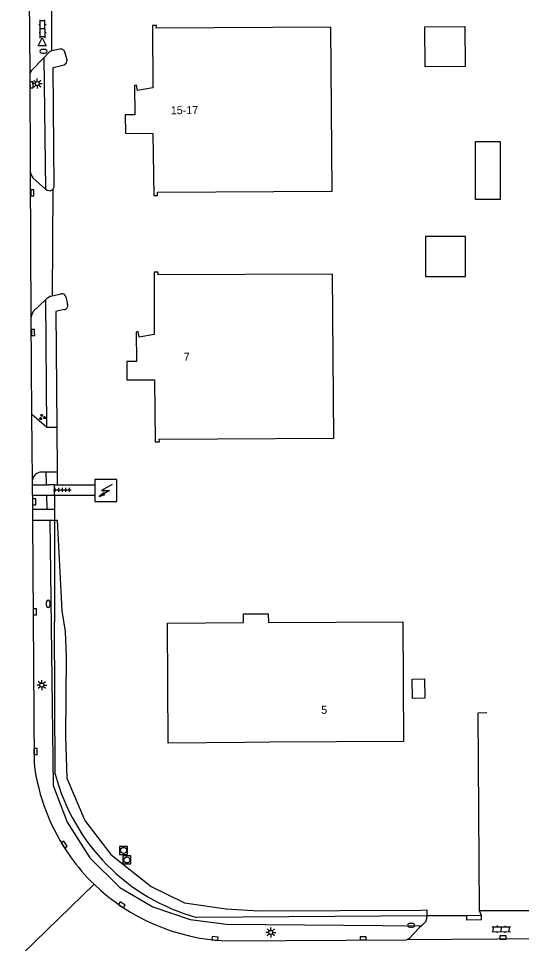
# Model space of a CAD drawing. Extents: x 131000 to 133013, y 393000 to 396501.
# Drawn here: x 132118.8 to 132181.7, y 394804.8 to 394920.3 of the extents above; entities that cross this region are included whole.
import ezdxf

# ---------------------------------------------------------------- set-up
doc = ezdxf.new("R2010")
doc.units = 0
for name, color, linetype in [('gg-afsc-erfafscheiding', 7, 'Continuous'), ('gg-afsc-hekwerk', 7, 'Continuous'), ('gg-anno-huisnummerreeks BGT', 7, 'Continuous'), ('gg-bbg-gedigitaliseerde bebouwing', 7, 'Continuous'), ('gg-bbg-gedigitaliseerde bijgebouw', 7, 'Continuous'), ('gg-bbg-hoofdgebouw', 7, 'Continuous'), ('gg-bbg-lage trafo', 7, 'Continuous'), ('gg-bbg-overig bouwwerk', 7, 'Continuous'), ('gg-bbg-toegangstrap', 7, 'Continuous'), ('gg-knt-verharding', 7, 'Continuous'), ('gt-grn-groengrens', 7, 'Continuous'), ('gt-grn-vlakafsluiter', 7, 'Continuous'), ('gt-grn-weggrens', 7, 'Continuous'), ('gt-symb-brandkraan', 7, 'Continuous'), ('gt-symb-groenvak', 7, 'Continuous'), ('gt-symb-klinker verharding', 7, 'Continuous'), ('gt-symb-kolk', 7, 'Continuous'), ('gt-symb-lichtmast', 7, 'Continuous'), ('gt-symb-rioolschacht', 7, 'Continuous'), ('gt-symb-tegel verharding', 7, 'Continuous'), ('gt-symb-trafo symbool', 7, 'Continuous'), ('gt-symb-waterafsluiter', 7, 'Continuous')]:
    doc.layers.add(name, color=color, linetype=linetype)

# ---------------------------------------------------------------- blocks, each defined once
blk = doc.blocks.new('gt0-GRVAK')
at = {"layer": 'gt-symb-groenvak'}
for p, q in [((-0.11, 0.19), (-0.23, 0.24)), ((-0.18, 0.15), (0.09, 0.15)), ((-0.09, 0.21), (-0.16, 0.32)), ((-0.05, 0.21), (-0.05, 0.39)), ((0, 0.21), (0.06, 0.32)), ((0.02, 0.19), (0.13, 0.24)), ((0.26, -0.05), (0.2, 0.06)), ((0.31, -0.05), (0.31, 0.13)), ((0.35, -0.05), (0.41, 0.06)), ((-0.24, -0.23), (-0.36, -0.18)), ((-0.32, -0.26), (-0.05, -0.26)), ((-0.23, -0.21), (-0.29, -0.09)), ((-0.18, -0.2), (-0.18, -0.02)), ((-0.14, -0.21), (-0.07, -0.09)), ((-0.12, -0.23), (0, -0.18)), ((0.24, -0.07), (0.12, -0.02)), ((0.17, -0.11), (0.44, -0.11)), ((0.37, -0.07), (0.49, -0.02))]:
    blk.add_line(p, q, dxfattribs=at)
blk = doc.blocks.new('gt0-KOLK')
at = {"layer": 'gt-symb-kolk'}
blk.add_lwpolyline([(0, 0), (0.37, 0), (0.37, 0.4), (-0.38, 0.4), (-0.38, 0), (0, 0)], dxfattribs=at)
blk = doc.blocks.new('gt0-KL1')
at = {"layer": 'gt-symb-klinker verharding'}
for p, q in [((-1.15, 0.3), (1.15, 0.3)), ((-1, -0.3), (-1, 0.3)), ((-0.5, 0.3), (-0.5, 0.45)), ((0, -0.3), (0, 0.3)), ((0.5, 0.3), (0.5, 0.45)), ((1, -0.3), (1, 0.3)), ((-1.15, -0.3), (1.15, -0.3)), ((-0.5, -0.45), (-0.5, -0.3)), ((0.5, -0.45), (0.5, -0.3))]:
    blk.add_line(p, q, dxfattribs=at)
blk = doc.blocks.new('gt0-LMAST')
at = {"layer": 'gt-symb-lichtmast'}
for p, q in [((-0.18, 0.17), (-0.45, 0.44)), ((-0.01, 0.25), (-0.01, 0.62)), ((0.17, 0.17), (0.44, 0.44)), ((-0.26, 0), (-0.63, 0)), ((-0.18, -0.18), (-0.45, -0.45)), ((-0.01, -0.25), (-0.01, -0.63)), ((0.44, -0.45), (0.17, -0.18)), ((0.24, 0), (0.62, 0))]:
    blk.add_line(p, q, dxfattribs=at)
blk.add_circle((-0.01, 0), 0.25, dxfattribs=at)
blk = doc.blocks.new('gt0-BR')
at = {"layer": 'gt-symb-brandkraan'}
for centre, radius, start, end in [((-0.24, 0), 0.206, 107.5669, 252.4331), ((0.6, -2.66), 3, 106.892, 107.5669), ((0, -0.69), 0.938, 73.108, 106.892), ((-0.6, -2.66), 3, 72.4331, 73.108), ((0.24, 0), 0.206, 287.567, 72.4331), ((0.6, 2.66), 3, 252.4331, 253.108), ((0, 0.69), 0.938, 253.108, 286.8921), ((-0.6, 2.66), 3, 286.8921, 287.567)]:
    blk.add_arc(centre, radius, start, end, dxfattribs=at)
blk = doc.blocks.new('gt0-TEG1')
at = {"layer": 'gt-symb-tegel verharding'}
for p, q in [((-1.12, 0), (1.12, 0)), ((-0.9, -0.25), (-0.9, 0.25)), ((-0.45, -0.25), (-0.45, 0.25)), ((0, -0.25), (0, 0.25)), ((0.45, -0.25), (0.45, 0.25)), ((0.9, -0.25), (0.9, 0.25))]:
    blk.add_line(p, q, dxfattribs=at)
blk = doc.blocks.new('gt0-HSP')
at = {"layer": 'gt-symb-trafo symbool'}
for points in [[(0.77, 0.75), (-0.53, 0), (0.47, 0), (-0.83, -0.75)], [(-0.22, -0.24), (-0.83, -0.75), (-0.08, -0.48)]]:
    blk.add_lwpolyline(points, dxfattribs=at)
blk = doc.blocks.new('gt0-WAFSL')
at = {"layer": 'gt-symb-waterafsluiter'}
for p, q in [((-0.5, -0.33), (0, 0.67)), ((0, 0.67), (0.5, -0.33)), ((0.5, -0.33), (-0.5, -0.33))]:
    blk.add_line(p, q, dxfattribs=at)
blk = doc.blocks.new('gt0-RS')
at = {"layer": 'gt-symb-rioolschacht'}
blk.add_lwpolyline([(-0.5, -0.5), (0.5, -0.5), (0.5, 0.5), (-0.5, 0.5)], close=True, dxfattribs=at)
blk.add_circle((0, 0), 0.375, dxfattribs=at)

msp = doc.modelspace()

# ---------------------------------------------------------------- linework, layer by layer
at = {"layer": 'gg-afsc-erfafscheiding'}
for p, q in [((132123.42, 394825.9), (132123.31, 394844.96)), ((132169.85, 394808.2), (132141.09, 394808.02)), ((132174.82, 394808.23), (132169.85, 394808.2)), ((132176.64, 394808.24), (132174.82, 394808.23))]:
    msp.add_line(p, q, dxfattribs=at)
msp.add_arc((132147.81, 394832.32), 25.22, 194.7562, 254.554, dxfattribs=at)
at = {"layer": 'gg-afsc-hekwerk'}
msp.add_line((132183.21, 394808.86), (132176.43, 394808.82), dxfattribs=at)
msp.add_lwpolyline([(132176.43, 394808.82), (132176.23, 394833.59), (132177.33, 394833.6)], dxfattribs=at)
at = {"layer": 'gg-bbg-gedigitaliseerde bebouwing'}
msp.add_lwpolyline([(132146.94, 394844.84), (132146.93, 394845.94), (132150.03, 394845.96), (132150.04, 394844.86)], dxfattribs=at)
at = {"layer": 'gg-bbg-gedigitaliseerde bijgebouw'}
for points in [[(132169.61, 394914.28), (132169.57, 394919.28), (132174.57, 394919.32), (132174.61, 394914.32), (132169.61, 394914.28)], [(132175.92, 394904.96), (132178.99, 394904.96), (132178.99, 394897.69), (132175.92, 394897.69), (132175.92, 394904.96)]]:
    msp.add_lwpolyline(points, dxfattribs=at)
at = {"layer": 'gg-bbg-hoofdgebouw'}
for points in [[(132136.04, 394919.09), (132136.06, 394919.43), (132135.56, 394919.43), (132135.61, 394911.66), (132133.71, 394911.33), (132133.55, 394912), (132133.32, 394911.96), (132133.37, 394908.27), (132132.17, 394908.28), (132132.18, 394905.97), (132135.63, 394905.95), (132135.72, 394898.22), (132136.21, 394898.22), (132136.2, 394898.61), (132158, 394898.75), (132157.84, 394919.23), (132136.04, 394919.09)], [(132136.26, 394888.29), (132136.26, 394888.64), (132135.79, 394888.64), (132135.76, 394880.85), (132133.91, 394880.51), (132133.76, 394881.19), (132133.53, 394881.13), (132133.56, 394877.47), (132132.37, 394877.45), (132132.38, 394875.16), (132135.83, 394875.16), (132135.92, 394867.41), (132136.43, 394867.42), (132136.42, 394867.77), (132158.22, 394867.9), (132158.06, 394888.38), (132136.26, 394888.29)], [(132150.04, 394844.86), (132166.84, 394844.95), (132166.92, 394829.99), (132150.18, 394829.92), (132147.06, 394829.86), (132137.54, 394829.79), (132137.45, 394844.79), (132146.94, 394844.84)]]:
    msp.add_lwpolyline(points, dxfattribs=at)
at = {"layer": 'gg-bbg-lage trafo'}
msp.add_line((132128.35, 394862.07), (132128.35, 394860.77), dxfattribs=at)
msp.add_lwpolyline([(132128.35, 394860.77), (132128.35, 394859.97), (132131.11, 394859.97), (132131.11, 394862.72), (132128.35, 394862.71), (132128.35, 394862.07)], dxfattribs=at)
at = {"layer": 'gg-bbg-overig bouwwerk'}
msp.add_lwpolyline([(132169.68, 394893.08), (132169.68, 394888.09), (132174.67, 394888.09), (132174.67, 394893.08), (132169.68, 394893.08)], dxfattribs=at)
at = {"layer": 'gg-bbg-toegangstrap'}
msp.add_lwpolyline([(132168, 394837.78), (132169.56, 394837.81), (132169.6, 394835.4), (132168.04, 394835.38), (132168, 394837.78)], dxfattribs=at)
at = {"layer": 'gg-knt-verharding'}
for p, q in [((132120.27, 394913.5), (132120.21, 394923.58)), ((132122.94, 394921.21), (132122.94, 394916.26)), ((132124, 394916.48), (132122.94, 394916.26)), ((132120.32, 394901.09), (132120.27, 394913.5)), ((132120.41, 394883), (132120.32, 394901.09)), ((132123.13, 394898.93), (132123.05, 394885.68)), ((132123.05, 394885.68), (132124.14, 394885.92)), ((132124.74, 394885.54), (132124.97, 394884.56)), ((132120.5, 394870.84), (132120.41, 394883)), ((132120.56, 394862.7), (132120.5, 394870.84)), ((132122.31, 394869.24), (132120.5, 394870.84)), ((132122.31, 394869.24), (132123.61, 394869.25)), ((132123.61, 394869.25), (132123.65, 394863.68)), ((132121.68, 394863.66), (132122.24, 394863.67)), ((132122.24, 394863.67), (132123.65, 394863.68)), ((132123.65, 394863.68), (132123.67, 394862.07)), ((132120.57, 394862.07), (132120.56, 394862.7)), ((132120.57, 394860.77), (132120.57, 394862.07)), ((132120.57, 394862.07), (132122.28, 394862.07)), ((132122.28, 394862.07), (132122.58, 394862.07)), ((132123.34, 394862.07), (132122.58, 394862.07)), ((132123.34, 394862.07), (132123.67, 394862.07)), ((132123.67, 394862.07), (132128.35, 394862.07)), ((132120.57, 394860.77), (132120.58, 394859.01)), ((132120.57, 394860.77), (132122.06, 394860.77)), ((132122.06, 394860.77), (132122.31, 394860.77)), ((132122.31, 394860.77), (132123.34, 394860.77)), ((132123.34, 394860.77), (132128.35, 394860.77)), ((132120.58, 394859.01), (132120.59, 394857.65)), ((132120.58, 394859.01), (132122.36, 394859.01)), ((132122.36, 394859.01), (132123.34, 394859.01)), ((132120.59, 394857.65), (132122.75, 394857.65)), ((132120.59, 394857.65), (132120.77, 394827.29)), ((132122.75, 394857.65), (132123.33, 394857.65)), ((132123.33, 394857.65), (132123.67, 394857.64)), ((132169.83, 394807.97), (132169.85, 394808.2)), ((132174.82, 394807.68), (132174.82, 394808.23)), ((132176.65, 394807.7), (132176.64, 394808.24)), ((132169.16, 394806.97), (132168.93, 394806.74)), ((132176.65, 394807.7), (132174.82, 394807.68)), ((132144.72, 394805.09), (132167.29, 394805.23)), ((132185.25, 394805.35), (132167.29, 394805.23))]:
    msp.add_line(p, q, dxfattribs=at)
for points in [[(132122, 394915.41), (132120.43, 394913.76), (132120.27, 394913.5)], [(132122.94, 394916.26), (132122.7, 394916.15), (132122, 394915.41)], [(132123.13, 394898.93), (132123.28, 394899.28), (132123.18, 394914.17), (132124.52, 394914.53), (132124.82, 394914.77), (132124.89, 394915.14), (132124.63, 394916.12)], [(132120.32, 394901.09), (132120.4, 394900.72), (132120.62, 394900.4), (132122.2, 394899)], [(132122.2, 394899), (132122.41, 394898.87), (132122.79, 394898.79), (132123.13, 394898.93)], [(132122.2, 394885.16), (132122.46, 394885.4), (132122.78, 394885.62), (132123.05, 394885.68)], [(132122.2, 394885.16), (132120.7, 394883.73), (132120.48, 394883.39), (132120.41, 394883)], [(132124.54, 394883.95), (132123.49, 394883.69), (132123.61, 394869.25)], [(132169.83, 394807.97), (132169.81, 394807.82), (132169.65, 394807.48), (132169.16, 394806.97)], [(132168.93, 394806.74), (132167.58, 394805.35), (132167.29, 394805.23)]]:
    msp.add_lwpolyline(points, dxfattribs=at)
for centre, radius, start, end in [((132124.13, 394915.99), 0.513, 14.586, 105.4769), ((132124.25, 394885.43), 0.501, 13.1763, 103.036), ((132124.54, 394884.41), 0.451, 270.0836, 20.0848), ((132121.75, 394862.45), 1.21, 93.166, 168.1294), ((132145.82, 394830.29), 25.22, 186.8141, 215.6538), ((132145.77, 394830.25), 25.17, 215.6512, 225.9318), ((132145.81, 394830.29), 25.22, 225.9195, 267.5203)]:
    msp.add_arc(centre, radius, start, end, dxfattribs=at)
at = {"layer": 'gt-grn-groengrens'}
for p, q in [((132122, 394915.41), (132122.2, 394899)), ((132122.2, 394885.16), (132122.31, 394869.24)), ((132122.24, 394863.67), (132122.28, 394862.07)), ((132122.31, 394860.77), (132122.36, 394859.01))]:
    msp.add_line(p, q, dxfattribs=at)
for points in [[(132122.75, 394857.65), (132123.16, 394824.48), (132124.9, 394819.92), (132127.74, 394815.47), (132131.48, 394811.76), (132135.59, 394809.35), (132140.27, 394807.75), (132144.83, 394807.16), (132169.16, 394806.97)], [(132123.67, 394857.64), (132124.26, 394846.33), (132124.67, 394843.74), (132124.79, 394840.57), (132124.69, 394830.62), (132124.85, 394825.43), (132127.1, 394820.12), (132130.37, 394815.89), (132135.39, 394811.9), (132139.57, 394809.84), (132144.77, 394809.07), (132148.82, 394808.85), (132169.09, 394808.94)]]:
    msp.add_lwpolyline(points, dxfattribs=at)
at = {"layer": 'gt-grn-vlakafsluiter'}
for p, q in [((132123.34, 394860.77), (132123.34, 394859.01)), ((132123.34, 394859.01), (132123.33, 394857.65)), ((132123.33, 394857.65), (132123.31, 394844.96)), ((132176.64, 394808.24), (132176.43, 394808.82))]:
    msp.add_line(p, q, dxfattribs=at)
msp.add_lwpolyline([(132169.09, 394808.94), (132169.84, 394808.95), (132169.85, 394808.2)], dxfattribs=at)
at = {"layer": 'gt-grn-weggrens'}
for p, q in [((132123.34, 394860.77), (132123.34, 394862.07)), ((132117.22, 394801.42), (132128.27, 394812.17))]:
    msp.add_line(p, q, dxfattribs=at)

# ---------------------------------------------------------------- block references
at = {"layer": 'gt-symb-brandkraan'}
for p in [(132121.96, 394916.21), (132167.88, 394807.03)]:
    msp.add_blockref('gt0-BR', p, dxfattribs=at)
at = {"layer": 'gt-symb-brandkraan', "rotation": 90.45835645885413}
msp.add_blockref('gt0-BR', (132122.54, 394847.19), dxfattribs=at)
at = {"layer": 'gt-symb-groenvak'}
msp.add_blockref('gt0-GRVAK', (132121.8, 394870.51), dxfattribs=at)
at = {"layer": 'gt-symb-klinker verharding'}
for p, rotation in [((132121.84, 394919.01), 90.68751635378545), ((132179.14, 394806.54), -0.9739344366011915)]:
    msp.add_blockref('gt0-KL1', p, dxfattribs=dict(at, rotation=rotation))
at = {"layer": 'gt-symb-kolk'}
for p, rotation in [((132120.67, 394912.02), 90.45835645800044), ((132120.76, 394898.54), 90.45835645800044), ((132120.85, 394881.09), 90.45835645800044), ((132120.58, 394859.94), -89.66107117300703), ((132121.07, 394846.21), 90.45835645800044), ((132121.16, 394828.74), 90.45835645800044), ((132124.37, 394817), -57.24756055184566), ((132131.63, 394809.43), -33.578813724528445), ((132143.37, 394805.18), -6.200970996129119)]:
    msp.add_blockref('gt0-KOLK', p, dxfattribs=dict(at, rotation=rotation))
for p in [(132161.88, 394805.21), (132179.35, 394805.32)]:
    msp.add_blockref('gt0-KOLK', p, dxfattribs=at)
at = {"layer": 'gt-symb-lichtmast'}
for p in [(132121.18, 394912.18), (132121.75, 394837.05), (132150.35, 394806.15)]:
    msp.add_blockref('gt0-LMAST', p, dxfattribs=at)
at = {"layer": 'gt-symb-rioolschacht'}
for p in [(132131.96, 394816.39), (132132.37, 394815.2)]:
    msp.add_blockref('gt0-RS', p, dxfattribs=at)
at = {"layer": 'gt-symb-tegel verharding'}
msp.add_blockref('gt0-TEG1', (132124.31, 394861.42), dxfattribs=at)
at = {"layer": 'gt-symb-trafo symbool'}
msp.add_blockref('gt0-HSP', (132129.74, 394861.33), dxfattribs=at)
at = {"layer": 'gt-symb-waterafsluiter'}
msp.add_blockref('gt0-WAFSL', (132121.8, 394917.23), dxfattribs=at)

# ---------------------------------------------------------------- texts
at = {"layer": 'gg-anno-huisnummerreeks BGT'}
for s, rotation, p in [('15-17', 0.4, (132137.86, 394908.35)), ('7', 0.3, (132139.47, 394877.55)), ('5', 0.2, (132156.64, 394833.45))]:
    msp.add_text(s, height=1, rotation=rotation, dxfattribs=at).set_placement(p)

doc.saveas('drawing.dxf')
